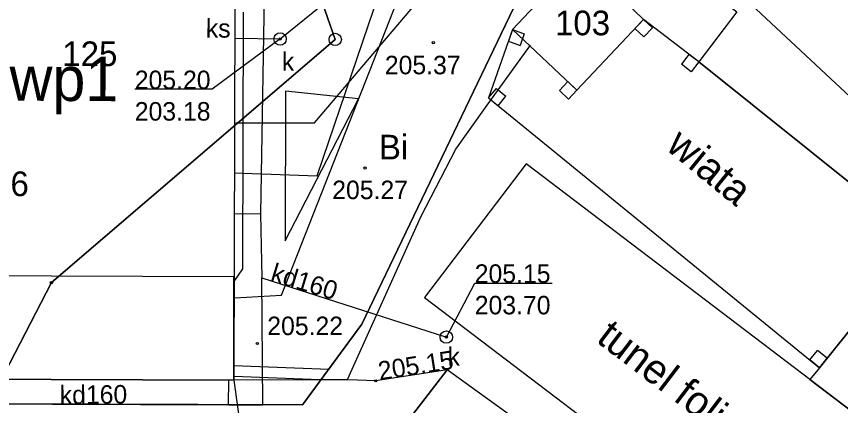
# Model space of a CAD drawing. Extents: x 6512606 to 6513006, y 6022524 to 6022728.
# Drawn here: x 6512750.51 to 6512783.87, y 6022633.88 to 6022649.64 of the extents above; entities that cross this region are included whole.
import ezdxf

# ---------------------------------------------------------------- set-up
doc = ezdxf.new("R2010")
doc.units = 0
for name, color, linetype in [('202-punkt graniczny', 7, 'Continuous'), ('203-punkt graniczny', 7, 'Continuous'), ('210-oznaczenie konturu użytku gruntowego', 7, 'Continuous'), ('211-numer działki ewidencyjnej', 7, 'Continuous'), ('217-kontur klasyfikacyjny', 7, 'Continuous'), ('218-kontur użytku gruntowego', 7, 'Continuous'), ('219-działka ewidencyjna', 7, 'Continuous'), ('312-budynek ewidencyjny', 7, 'Continuous'), ('312-oznaczenie budynku ewidencyjnego', 7, 'Continuous'), ('320-blok - kondygnacja nadziemna', 7, 'Continuous'), ('4', 7, 'Continuous'), ('chodnik', 7, 'Continuous'), ('chodnik (powierzchnia)', 7, 'Continuous'), ('Default', 7, 'Continuous'), ('inna budowla', 7, 'Continuous'), ('Komentarz lub etykieta na mapie', 7, 'Continuous'), ('Level 47', 7, 'Continuous'), ('obszar utwardzony', 7, 'Continuous'), ('ogrodzenie trwałe', 7, 'Continuous'), ('pikieta sztuczna', 7, 'Continuous'), ('pikieta sztuczna-Atr2', 7, 'Continuous'), ('przewód elektroenergetyczny (linia)', 7, 'Continuous'), ('przewód gazowy (linia)', 7, 'Continuous'), ('przewód kanalizacyjny (linia)', 7, 'Continuous'), ('przewód kanalizacyjny (linia)-Atr1', 7, 'Continuous'), ('przewód wodociągowy (linia)', 7, 'Continuous'), ('punkt o określonej wysokości (sieć kanalizacyjna)', 7, 'Continuous'), ('punkt o określonej wysokości (sieć kanalizacyjna)-Atr2', 7, 'Continuous'), ('punkt o określonej wysokości (sieć kanalizacyjna)-Atr3', 7, 'Continuous'), ('wiata', 7, 'Continuous'), ('właz okrągły - siec kanalizacyjna (punkt)', 7, 'Continuous'), ('właz okrągły - siec kanalizacyjna (punkt)-Atr17', 7, 'Continuous')]:
    doc.layers.add(name, color=color, linetype=linetype)

# ---------------------------------------------------------------- blocks, each defined once
blk = doc.blocks.new('202')
at = {"layer": 'Default'}
blk.add_circle((0, 0), 2.5, dxfattribs=at)
blk = doc.blocks.new('203')
at = {"layer": 'Default'}
blk.add_circle((0, 0), 0.45, dxfattribs=at)
blk = doc.blocks.new('PW01')
at = {"layer": 'Default'}
blk.add_circle((0, 0), 0.45, dxfattribs=at)
blk = doc.blocks.new('US22')
at = {"layer": 'Default'}
blk.add_circle((0, 0), 2.5, dxfattribs=at)
blk = doc.blocks.new('IB10')
at = {"layer": 'Default'}
for p, q in [((0, 0), (0, 5)), ((0, 5), (5, 5)), ((5, 0), (5, 5)), ((0, 0), (5, 0))]:
    blk.add_line(p, q, dxfattribs=at)

msp = doc.modelspace()

# ---------------------------------------------------------------- linework, layer by layer
at = {"layer": '217-kontur klasyfikacyjny'}
for points in [[(6512772.25, 6022653.37), (6512764.49, 6022637.17)], [(6512764.49, 6022637.17), (6512762.09, 6022633.91)], [(6512762.09, 6022633.91), (6512749.37, 6022633.95)]]:
    msp.add_lwpolyline(points, dxfattribs=at)
at = {"layer": '218-kontur użytku gruntowego'}
for points in [[(6512772.25, 6022653.37), (6512764.49, 6022637.17)], [(6512764.49, 6022637.17), (6512772.25, 6022653.37)], [(6512763.41, 6022648.71), (6512762.17, 6022652.29)], [(6512762.17, 6022652.29), (6512763.41, 6022648.71)], [(6512751.92, 6022638.86), (6512763.41, 6022648.71)], [(6512763.41, 6022648.71), (6512751.92, 6022638.86)], [(6512749.37, 6022633.95), (6512751.92, 6022638.86)], [(6512751.92, 6022638.86), (6512749.37, 6022633.95)], [(6512764.49, 6022637.17), (6512762.09, 6022633.91)], [(6512762.09, 6022633.91), (6512764.49, 6022637.17)], [(6512762.09, 6022633.91), (6512749.37, 6022633.95)], [(6512749.37, 6022633.95), (6512762.09, 6022633.91)]]:
    msp.add_lwpolyline(points, dxfattribs=at)
at = {"layer": '219-działka ewidencyjna'}
for points in [[(6512763.41, 6022648.71), (6512762.17, 6022652.29)], [(6512763.41, 6022648.71), (6512751.92, 6022638.86)], [(6512751.92, 6022638.86), (6512735.75, 6022607.64)]]:
    msp.add_lwpolyline(points, dxfattribs=at)
at = {"layer": '312-budynek ewidencyjny'}
msp.add_lwpolyline([(6512770.59, 6022649.11), (6512773.32, 6022652.02), (6512775.89, 6022649.52), (6512773.2, 6022646.66)], close=True, dxfattribs=at)
for points in [[(6512759.35, 6022650.21), (6512759.3, 6022634.91)], [(6512759.3, 6022634.91), (6512748.2, 6022634.95)]]:
    msp.add_lwpolyline(points, dxfattribs=at)
at = {"layer": '320-blok - kondygnacja nadziemna'}
msp.add_lwpolyline([(6512759.31, 6022639.09), (6512748.21, 6022639.13), (6512748.2, 6022634.95), (6512759.3, 6022634.91)], close=True, dxfattribs=at)
at = {"layer": '4'}
for points in [[(6512763.41, 6022648.71), (6512762.17, 6022652.29)], [(6512763.41, 6022648.71), (6512751.92, 6022638.86)], [(6512751.92, 6022638.86), (6512735.75, 6022607.64)]]:
    msp.add_lwpolyline(points, dxfattribs=at)
at = {"layer": 'chodnik'}
for points in [[(6512759.68, 6022649.82), (6512759.66, 6022639.42), (6512759.31, 6022638.9), (6512759.31, 6022635.5), (6512763.16, 6022635.35), (6512764.49, 6022637.17), (6512772.25, 6022653.37)], [(6512764.23, 6022630.5), (6512767.94, 6022635.33), (6512765.05, 6022634.88), (6512763.94, 6022634.92), (6512759.3, 6022634.91), (6512760.25, 6022628.06)]]:
    msp.add_lwpolyline(points, dxfattribs=at)
at = {"layer": 'chodnik (powierzchnia)'}
msp.add_lwpolyline([(6512761.39, 6022640.55), (6512764.35, 6022646.3), (6512761.4, 6022646.62)], close=True, dxfattribs=at)
at = {"layer": 'inna budowla'}
for points in [[(6512767.02, 6022638.26), (6512783.18, 6022625.97), (6512787.3, 6022631.38), (6512771.14, 6022643.67)], [(6512764.23, 6022630.5), (6512778.87, 6022619.65), (6512782.6, 6022624.74), (6512767.94, 6022635.33)]]:
    msp.add_lwpolyline(points, close=True, dxfattribs=at)
at = {"layer": 'obszar utwardzony'}
msp.add_lwpolyline([(6512775.13, 6022653.27), (6512779.67, 6022649.83), (6512778.13, 6022647.8), (6512787.16, 6022640.57), (6512783.02, 6022635.41), (6512782.63, 6022634.93), (6512787.3, 6022631.38), (6512783.18, 6022625.97), (6512782.4, 6022624.88), (6512782.6, 6022624.74), (6512781.28, 6022622.94), (6512787.17, 6022619.72)], dxfattribs=at)
at = {"layer": 'ogrodzenie trwałe'}
msp.add_lwpolyline([(6512759.3, 6022635.07), (6512762.44, 6022634.95), (6512763.91, 6022634.93), (6512766.88, 6022641.52), (6512768.3, 6022644.27), (6512769.5, 6022645.95), (6512771.32, 6022648.48)], dxfattribs=at)
at = {"layer": 'przewód elektroenergetyczny (linia)'}
msp.add_lwpolyline([(6512759.34, 6022638.24), (6512761.23, 6022638.35), (6512771.78, 6022665.17)], dxfattribs=at)
at = {"layer": 'przewód gazowy (linia)'}
msp.add_lwpolyline([(6512759.32, 6022643.31), (6512762.68, 6022643.19), (6512770.72, 6022666.88)], dxfattribs=at)
at = {"layer": 'przewód kanalizacyjny (linia)'}
for points in [[(6512750.63, 6022659.53), (6512750.53, 6022662.41), (6512746.52, 6022662.45), (6512746.43, 6022659.54), (6512745.45, 6022659.51), (6512745.46, 6022656.91), (6512745.52, 6022641.51), (6512745.53, 6022639.13), (6512748.39, 6022633.94), (6512759.09, 6022633.91), (6512760.48, 6022633.91), (6512760.44, 6022639.05)], [(6512755.36, 6022659.54), (6512755.4, 6022662.35), (6512760.42, 6022662.29), (6512760.64, 6022656.88), (6512760.38, 6022641.64), (6512760.44, 6022639.05)], [(6512761.18, 6022648.73), (6512774.9, 6022659.84), (6512776.9, 6022659.48)], [(6512780.05, 6022650.33), (6512790.7, 6022640.38)], [(6512759.36, 6022648.76), (6512761.18, 6022648.73)], [(6512759.32, 6022641.66), (6512760.38, 6022641.64)], [(6512760.44, 6022639.05), (6512767.91, 6022636.65)], [(6512759.09, 6022633.91), (6512759.1, 6022634.91)]]:
    msp.add_lwpolyline(points, dxfattribs=at)
at = {"layer": 'przewód wodociągowy (linia)'}
msp.add_lwpolyline([(6512759.39, 6022645.33), (6512762.57, 6022645.33), (6512773.55, 6022658.26), (6512774.3, 6022659.21)], dxfattribs=at)
at = {"layer": 'punkt o określonej wysokości (sieć kanalizacyjna)-Atr2'}
for points in [[(6512761.18, 6022648.73), (6512758.43, 6022646.69), (6512755.295, 6022646.69)], [(6512767.91, 6022636.65), (6512769.06, 6022638.84), (6512772.195, 6022638.84)]]:
    msp.add_lwpolyline(points, dxfattribs=at)
at = {"layer": 'wiata'}
msp.add_lwpolyline([(6512769.62, 6022646.34), (6512783.02, 6022635.41), (6512787.16, 6022640.57), (6512778.13, 6022647.8), (6512775.89, 6022649.52), (6512773.2, 6022646.66), (6512770.59, 6022649.11)], close=True, dxfattribs=at)

# ---------------------------------------------------------------- block references
at = {"layer": '202-punkt graniczny', "xscale": 0.1, "yscale": 0.10000000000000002}
msp.add_blockref('202', (6512763.41, 6022648.71), dxfattribs=at)
at = {"layer": '203-punkt graniczny', "xscale": 0.1, "yscale": 0.10000000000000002}
msp.add_blockref('203', (6512751.92, 6022638.86), dxfattribs=at)
at = {"layer": 'pikieta sztuczna', "xscale": 0.1, "yscale": 0.10000000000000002}
for p in [(6512767.38, 6022648.58), (6512764.62, 6022643.5), (6512760.26, 6022636.39), (6512765.05, 6022634.88)]:
    msp.add_blockref('PW01', p, dxfattribs=at)
at = {"layer": 'punkt o określonej wysokości (sieć kanalizacyjna)', "xscale": 0.1, "yscale": 0.10000000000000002}
for p in [(6512761.18, 6022648.73), (6512767.91, 6022636.65)]:
    msp.add_blockref('PW01', p, dxfattribs=at)
at = {"layer": 'wiata'}
for p, xscale, yscale, rotation in [((6512775.89, 6022649.52), 0.09999999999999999, 0.10000000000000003, -133.246), ((6512770.59, 6022649.11), 0.1, 0.09999999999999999, -109.29899999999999), ((6512778.13, 6022647.8), 0.1, 0.09999999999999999, 142.481), ((6512773.2, 6022646.66), 0.1, 0.10000000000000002, 136.811), ((6512769.62, 6022646.34), 0.1, 0.10000000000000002, -39.202999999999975), ((6512783.02, 6022635.41), 0.1, 0.10000000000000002, 51.259)]:
    msp.add_blockref('IB10', p, dxfattribs=dict(at, xscale=xscale, yscale=yscale, rotation=rotation))
at = {"layer": 'właz okrągły - siec kanalizacyjna (punkt)', "xscale": 0.1, "yscale": 0.10000000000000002}
for p in [(6512761.18, 6022648.73), (6512767.91, 6022636.65)]:
    msp.add_blockref('US22', p, dxfattribs=at)

# ---------------------------------------------------------------- texts
at = {"layer": '210-oznaczenie konturu użytku gruntowego'}
msp.add_text('Bi', height=1, dxfattribs=at).set_placement((6512765.18, 6022643.85))
at = {"layer": '211-numer działki ewidencyjnej'}
msp.add_text('1/56', height=1, dxfattribs=at).set_placement((6512748.403, 6022642.362))
at = {"layer": '312-oznaczenie budynku ewidencyjnego'}
for s, p in [('103', (6512772.31, 6022648.88)), ('125', (6512752.36, 6022647.63))]:
    msp.add_text(s, height=1, dxfattribs=at).set_placement(p)
at = {"layer": 'Komentarz lub etykieta na mapie'}
for s, rotation, p in [('wiata', 320.797, (6512776.75, 6022644.28)), ('tunel foliowy', 322.746, (6512773.93, 6022636.49))]:
    msp.add_text(s, height=1.2, rotation=rotation, dxfattribs=at).set_placement(p)
at = {"layer": 'Level 47'}
msp.add_text('wp1', height=1.7971, rotation=359.7281, dxfattribs=at).set_placement((6512750.219, 6022646.23))
at = {"layer": 'pikieta sztuczna-Atr2'}
for s, p in [('205.37', (6512765.42, 6022647.3)), ('205.27', (6512763.29, 6022642.24)), ('205.22', (6512760.66, 6022636.73))]:
    msp.add_text(s, height=0.75, dxfattribs=at).set_placement(p)
msp.add_text('205.15', height=0.75, rotation=8.85, dxfattribs=at).set_placement((6512765.21, 6022634.9))
at = {"layer": 'przewód kanalizacyjny (linia)-Atr1'}
for s, rotation, p in [('ks', 359.685, (6512758.17, 6022648.79)), ('kd160', 343.021, (6512760.75, 6022638.94)), ('kd160', 0.642, (6512752.26, 6022633.93))]:
    msp.add_text(s, height=0.75, rotation=rotation, dxfattribs=at).set_placement(p)
at = {"layer": 'punkt o określonej wysokości (sieć kanalizacyjna)-Atr2'}
for s, p in [('205.20', (6512755.295, 6022646.698)), ('205.15', (6512769.06, 6022638.848))]:
    msp.add_text(s, height=0.75, dxfattribs=at).set_placement(p)
at = {"layer": 'punkt o określonej wysokości (sieć kanalizacyjna)-Atr3'}
for s, p in [('203.18', (6512755.295, 6022645.423)), ('203.70', (6512769.06, 6022637.572))]:
    msp.add_text(s, height=0.75, dxfattribs=at).set_placement(p)
at = {"layer": 'właz okrągły - siec kanalizacyjna (punkt)-Atr17'}
for p in [(6512761.25, 6022647.44), (6512767.96, 6022635.49)]:
    msp.add_text('k', height=0.75, dxfattribs=at).set_placement(p)

doc.saveas('drawing.dxf')
